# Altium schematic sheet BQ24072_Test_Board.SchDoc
size A4
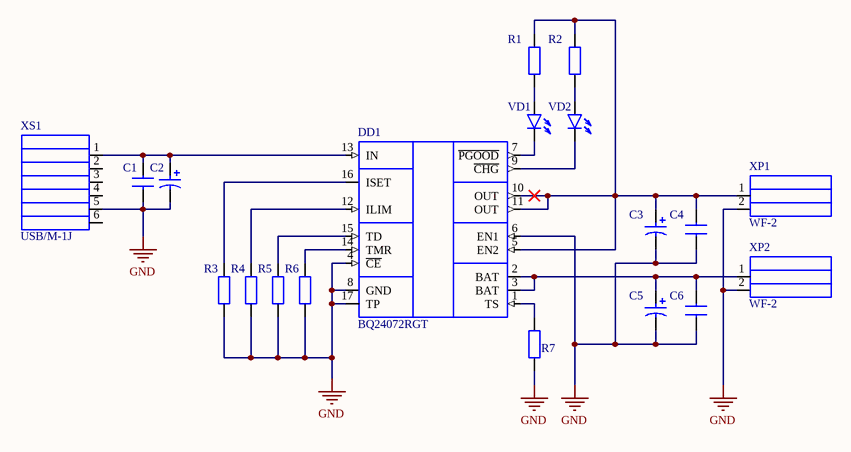
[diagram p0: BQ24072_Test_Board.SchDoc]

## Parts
C1  C <0603> 0,1 мкФ±20% 25В  [0603]  (value not drawn)
C2  B45197A3106  [B-3528-31]  (value not drawn)
C3  B45197A3106  [B-3528-31]  (value not drawn)
C4  C <0603> 0,1 мкФ±20% 25В  [0603]  (value not drawn)
C5  B45197A3106  [B-3528-31]  (value not drawn)
C6  C <0603> 0,1 мкФ±20% 25В  [0603]  (value not drawn)
DD1  BQ24072RGT  [QFN-16 (MO-220VEED-4)]
R1  R0603-820 Ом-5%  [0603]  (value not drawn)
R2  R0603-820 Ом-5%  [0603]  (value not drawn)
R3  R0603-3кОм-5%  [0603]  (value not drawn)
R4  R0603-1,1кОм-5%  [0603]  (value not drawn)
R5  R0603-1 Ом-5%  [0603]  (value not drawn)
R6  R0603-1 Ом-5%  [0603]  (value not drawn)
R7  R0603-10кОм-5%  [0603]  (value not drawn)
VD1  0805_LED_GREEN  [0805_LED_GREEN]  (value not drawn)
VD2  0805_LED_BLUE  [0805_LED_BLUE]  (value not drawn)
XP1  WF-2  [WF-2]
XP2  WF-2  [WF-2]
XS1  USB/M-1J  [USB/M-1J]

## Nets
GND: C1.1 C2.2 C3.2 C4.1 C5.2 C6.1 DD1.4(~{CE}) DD1.6(EN1) DD1.8(GND) DD1.17(TP) R3.1 R4.1 R5.1 R6.1 R7.1 XP1.2 XP2.2 XS1.5
NetC1_2: C1.2 C2.1 DD1.13(IN) XS1.1
NetC3_1: C3.1 C4.2 DD1.5(EN2) DD1.10(OUT) DD1.11(OUT) R1.1 R2.1 XP1.1
NetC5_1: C5.1 C6.2 DD1.2(BAT) DD1.3(BAT) XP2.1
NetDD1_1: DD1.1(TS) R7.2
NetDD1_7: DD1.7(~{PGOOD}) VD1.2
NetDD1_9: DD1.9(~{CHG}) VD2.2
NetDD1_12: DD1.12(ILIM) R4.2
NetDD1_14: DD1.14(TMR) R6.2
NetDD1_15: DD1.15(TD) R5.2
NetDD1_16: DD1.16(ISET) R3.2
NetR1_2: R1.2 VD1.1
NetR2_2: R2.2 VD2.1

Not connected (* = marked no-connect by the designer): XS1 2 3 4 6

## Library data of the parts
C1 C4 C6 = C <0603> 0,1 мкФ±20% 25В: Library Reference: C0603-10нФ-5%
C2 C3 C5 = B45197A3106: Tantalum Chip Capacitors; Low ESR; Value: 10мкФ 16В
DD1 = BQ24072RGT: 1.5A USB-FriendlyLi-Ion battery charger and Power-Path management IC; Manufacturer: Texas Instruments
R1 R2 = R0603-820 Ом-5%: Value: 820 Ом
R3 = R0603-3кОм-5%: Value: 3 кОм
R4 = R0603-1,1кОм-5%: Value: 1,1 кОм
R5 R6 = R0603-1 Ом-5%: Value: 1 Ом
R7 = R0603-10кОм-5%: Value: 10 кОм
VD1 = 0805_LED_GREEN: Светодиод SMD типоразмер 0805
VD2 = 0805_LED_BLUE: Светодиод SMD типоразмер 0805
XP1 XP2 = WF-2: Разъем питания 2 конт.(п) шаг 2,54 на плату
XS1 = USB/M-1J: Разъем miniUSB (м) на плату, 5 контактов, поверхност. монтаж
